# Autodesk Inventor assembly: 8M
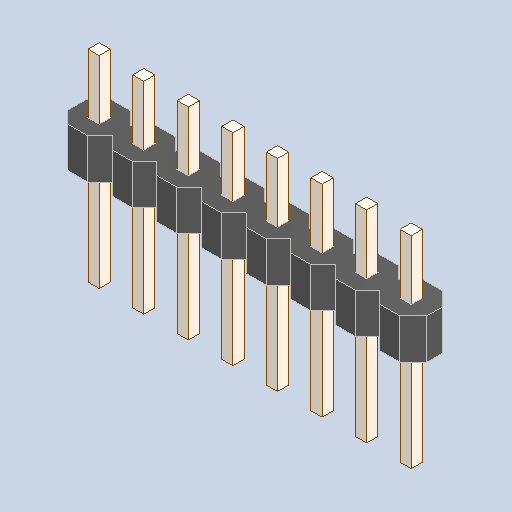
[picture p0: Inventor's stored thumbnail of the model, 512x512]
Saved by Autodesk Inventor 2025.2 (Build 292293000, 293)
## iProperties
Created: 2025-04
Part Number: 8M
Description: PART--DESC
Document SubType Name: Assembly
Designer: BennF
Author: BennF
Revision Number: NONE
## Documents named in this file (3)
- C:\Users\BennF\Nextcloud\Benutzer\CNC JarBeRi\existing parts\Electronics\RepRap A4988 Shied (USE WITHOUT ARDUINO)\reprap-a4988-1.snapshot.1\RepRap\RepRap\8M_4.iam
- C:\Users\BennF\Nextcloud\Benutzer\CNC JarBeRi\existing parts\Electronics\RepRap A4988 Shied (USE WITHOUT ARDUINO)\reprap-a4988-1.snapshot.1\RepRap\RepRap\8M Geometry.ipt
- C:\Users\BennF\Nextcloud\Benutzer\CNC JarBeRi\existing parts\Electronics\RepRap A4988 Shied (USE WITHOUT ARDUINO)\reprap-a4988-1.snapshot.1\RepRap\RepRap\pin4.ipt
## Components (2 placed, 2 different names)
1. 8M Geometry
2. pin4
